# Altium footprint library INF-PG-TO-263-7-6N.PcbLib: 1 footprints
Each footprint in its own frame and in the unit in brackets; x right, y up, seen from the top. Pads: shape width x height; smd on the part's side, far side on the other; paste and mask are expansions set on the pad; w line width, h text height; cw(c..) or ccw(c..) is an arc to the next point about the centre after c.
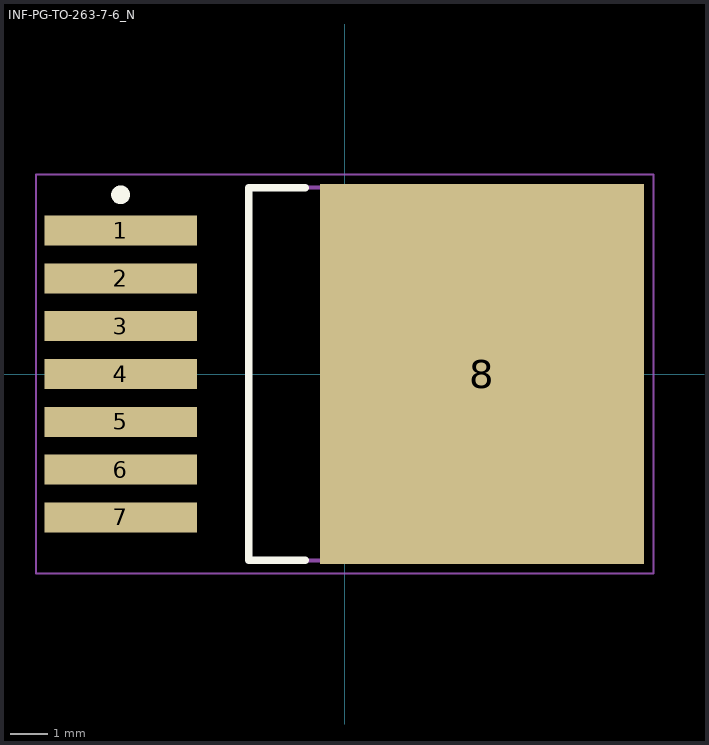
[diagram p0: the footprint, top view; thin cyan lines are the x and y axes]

## INF-PG-TO-263-7-6_N [mm] "DPAK, 7-Leads, Body 9.9x9.2mm, Pitch 1.27mm, IPC Medium Density"
height 4.4
pads (8):
  rect 4.05x0.8 smd: 1(-5.95,3.81) 2(-5.95,2.54) 3(-5.95,1.27) 4(-5.95,0) 5(-5.95,-1.27) 6(-5.95,-2.54) 7(-5.95,-3.81)
  rect 8.6x10.1 smd: 8(3.65,0)
Top Overlay:
  circle w0.25: c-5.95,4.76 r0.125
  lines w0.2: -1.05,-4.95 -2.55,-4.95 -2.55,4.95 -1.05,4.95
Mechanical 13:
  lines w0.1: -2.55,-4.95 -2.55,4.95 6.85,4.95 6.85,-4.95 -2.55,-4.95
Mechanical 15:
  lines w0.05: -8.2,-5.3 -8.2,5.3 8.2,5.3 8.2,-5.3 -8.2,-5.3
  lines w0.1: -0.5,0 0.5,0 ; 0,-0.5 0,0.5
3D body: height 4.4, standoff 0.1, extent -2.55,-4.95 6.85,4.95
